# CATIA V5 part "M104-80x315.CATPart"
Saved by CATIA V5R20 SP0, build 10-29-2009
Part number: M104-80x315
Source: Unknown
Bounding box of the stored display mesh (mm): x -39.842 to 39.842, y -39.842 to 39.842, z 0 to 315
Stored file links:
  C:\Users\Utente\Desktop\IO LAVORO\3D X SITO CF\X SITO\M104\M104-80x315.CATPart
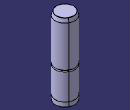
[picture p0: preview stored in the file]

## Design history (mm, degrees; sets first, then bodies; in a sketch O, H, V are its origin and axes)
Body1 (main body)
  Solid1 "PartBody": solid without history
